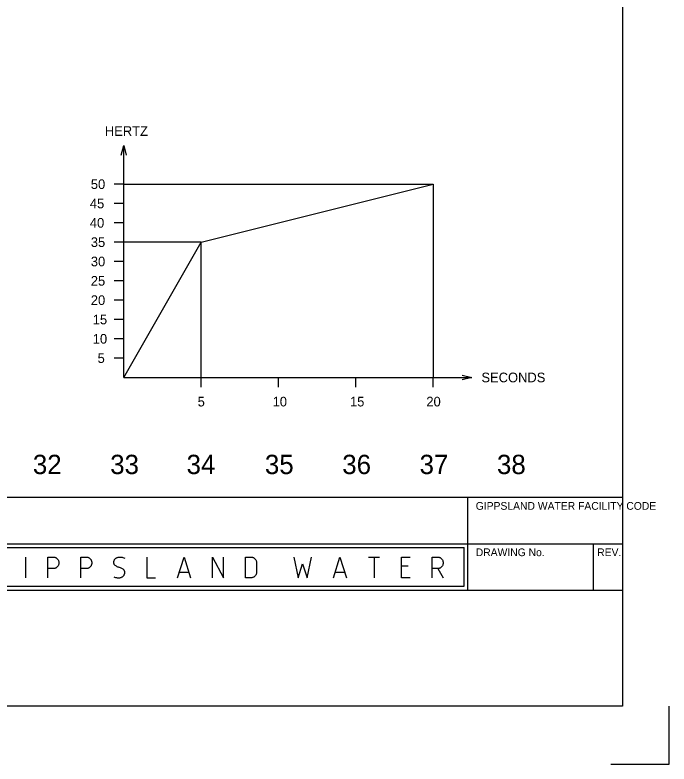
# Model space of a CAD drawing. Extents: x 0 to 841, y 0 to 594.
# Drawn here: x 671.9 to 841, y 0 to 193.8 of the extents above; entities that cross this region are included whole.
import ezdxf

# ---------------------------------------------------------------- set-up
doc = ezdxf.new("R2010")
doc.units = 0
doc.layers.add('A1BORDER', color=7, linetype='Continuous')
doc.layers.add('Level 1', color=7, linetype='Continuous')

msp = doc.modelspace()

# ---------------------------------------------------------------- linework, layer by layer
at = {"layer": 'A1BORDER'}
for p, q in [((829, 581), (829, 15)), ((592.5, 69), (829, 69)), ((789, 45), (789, 69)), ((28, 57), (829, 57)), ((821.5, 45), (821.5, 57)), ((637, 56), (788, 56)), ((788, 46), (788, 56)), ((663, 46), (788, 46)), ((664, 45), (829, 45)), ((829, 15), (28, 15)), ((829, 15), (829, 15)), ((841, 0), (841, 15)), ((826, 0), (841, 0))]:
    msp.add_line(p, q, dxfattribs=at)
for points in [[(674.74, 48.16), (674.74, 53.54)], [(680.42, 48.16), (680.42, 53.54), (681.84, 53.54), (681.96, 53.54), (682.08, 53.52), (682.2, 53.49), (682.32, 53.45), (682.43, 53.4), (682.54, 53.34), (682.65, 53.27), (682.74, 53.19), (682.84, 53.1), (682.92, 53), (682.99, 52.9), (683.06, 52.79), (683.12, 52.67), (683.17, 52.56), (683.21, 52.43), (683.23, 52.31), (683.25, 52.18), (683.26, 52.05), (683.25, 51.91), (683.23, 51.78), (683.21, 51.66), (683.17, 51.53), (683.12, 51.42), (683.06, 51.3), (682.99, 51.19), (682.92, 51.09), (682.84, 50.99), (682.74, 50.9), (682.65, 50.82), (682.54, 50.75), (682.43, 50.69), (682.32, 50.64), (682.2, 50.6), (682.08, 50.57), (681.96, 50.55), (681.84, 50.55), (680.42, 50.55)], [(688.93, 48.16), (688.93, 53.54), (690.35, 53.54), (690.47, 53.54), (690.59, 53.52), (690.71, 53.49), (690.83, 53.45), (690.94, 53.4), (691.05, 53.34), (691.16, 53.27), (691.26, 53.19), (691.35, 53.1), (691.43, 53), (691.51, 52.9), (691.57, 52.79), (691.63, 52.67), (691.68, 52.56), (691.72, 52.43), (691.75, 52.31), (691.76, 52.18), (691.77, 52.05), (691.76, 51.91), (691.75, 51.78), (691.72, 51.66), (691.68, 51.53), (691.63, 51.42), (691.57, 51.3), (691.51, 51.19), (691.43, 51.09), (691.35, 50.99), (691.26, 50.9), (691.16, 50.82), (691.05, 50.75), (690.94, 50.69), (690.83, 50.64), (690.71, 50.6), (690.59, 50.57), (690.47, 50.55), (690.35, 50.55), (688.93, 50.55)], [(697.45, 48.46), (697.67, 48.36), (697.9, 48.27), (698.12, 48.21), (698.36, 48.17), (698.6, 48.16), (698.84, 48.16), (698.87, 48.16), (699.03, 48.18), (699.18, 48.21), (699.33, 48.26), (699.48, 48.32), (699.62, 48.4), (699.72, 48.46), (699.81, 48.53), (699.9, 48.61), (699.98, 48.69), (700.05, 48.78), (700.11, 48.88), (700.17, 48.99), (700.22, 49.09), (700.25, 49.21), (700.28, 49.32), (700.29, 49.36), (700.3, 49.44), (700.3, 49.52), (700.3, 49.61), (700.29, 49.69), (700.27, 49.77), (700.25, 49.86), (700.22, 49.93), (700.18, 50.01), (700.14, 50.09), (700.09, 50.15), (700.04, 50.21), (700.01, 50.25), (699.85, 50.39), (699.69, 50.51), (699.52, 50.61), (699.34, 50.7), (699.15, 50.78), (698.95, 50.83), (698.87, 50.85), (698.68, 50.9), (698.49, 50.96), (698.3, 51.04), (698.12, 51.14), (697.96, 51.26), (697.8, 51.39), (697.73, 51.45), (697.67, 51.51), (697.62, 51.57), (697.58, 51.64), (697.53, 51.71), (697.5, 51.79), (697.47, 51.87), (697.46, 51.95), (697.44, 52.04), (697.43, 52.12), (697.43, 52.21), (697.44, 52.29), (697.45, 52.35), (697.47, 52.46), (697.51, 52.58), (697.55, 52.69), (697.61, 52.79), (697.67, 52.89), (697.74, 52.99), (697.82, 53.07), (697.9, 53.15), (697.99, 53.23), (698.02, 53.24), (698.15, 53.33), (698.3, 53.4), (698.44, 53.45), (698.6, 53.5), (698.75, 53.52), (698.87, 53.54), (699.11, 53.55), (699.35, 53.53), (699.58, 53.49), (699.82, 53.43), (700.04, 53.35), (700.27, 53.25)], [(705.96, 53.54), (705.96, 48.16), (708.23, 48.16)], [(713.91, 48.16), (715.61, 53.54), (717.32, 48.16)], [(722.99, 48.16), (722.99, 53.54), (725.83, 48.16), (725.83, 53.54)], [(731.52, 48.16), (731.52, 53.54), (732.94, 53.54), (733.06, 53.54), (733.18, 53.52), (733.3, 53.49), (733.42, 53.45), (733.53, 53.4), (733.64, 53.34), (733.75, 53.27), (733.84, 53.19), (733.94, 53.1), (734.02, 53), (734.09, 52.9), (734.16, 52.79), (734.22, 52.67), (734.27, 52.56), (734.31, 52.43), (734.33, 52.31), (734.35, 52.18), (734.36, 52.05), (734.36, 49.66), (734.35, 49.52), (734.33, 49.39), (734.31, 49.27), (734.27, 49.14), (734.22, 49.02), (734.16, 48.91), (734.09, 48.8), (734.02, 48.7), (733.94, 48.6), (733.84, 48.51), (733.75, 48.43), (733.64, 48.36), (733.53, 48.3), (733.42, 48.25), (733.3, 48.21), (733.18, 48.18), (733.06, 48.16), (732.94, 48.16), (731.52, 48.16)], [(744.01, 53.54), (745.14, 48.16), (746.28, 51.75), (747.41, 48.16), (748.55, 53.54)], [(754.22, 48.16), (755.92, 53.54), (757.63, 48.16)], [(763.31, 53.54), (766.15, 53.54)], [(764.73, 53.54), (764.73, 48.16)], [(774.09, 48.16), (771.82, 48.16), (771.82, 53.54), (774.09, 53.54)], [(779.78, 48.16), (779.78, 53.54), (781.2, 53.54), (781.32, 53.54), (781.44, 53.52), (781.56, 53.49), (781.68, 53.45), (781.79, 53.4), (781.9, 53.34), (782.01, 53.27), (782.1, 53.19), (782.2, 53.1), (782.28, 53), (782.35, 52.9), (782.42, 52.79), (782.48, 52.67), (782.53, 52.56), (782.56, 52.43), (782.59, 52.31), (782.61, 52.18), (782.61, 52.05), (782.61, 51.91), (782.59, 51.78), (782.56, 51.66), (782.53, 51.53), (782.48, 51.42), (782.42, 51.3), (782.35, 51.19), (782.28, 51.09), (782.2, 50.99), (782.1, 50.9), (782.01, 50.82), (781.9, 50.75), (781.79, 50.69), (781.68, 50.64), (781.56, 50.6), (781.44, 50.57), (781.32, 50.55), (781.2, 50.55), (779.78, 50.55)], [(773.53, 51.15), (771.82, 51.15)], [(781.2, 50.55), (782.61, 48.16)], [(714.48, 49.66), (716.75, 49.66)], [(754.79, 49.66), (757.06, 49.66)]]:
    msp.add_lwpolyline(points, dxfattribs=at)
at = {"layer": 'Level 1'}
for p, q in [((700, 100), (700, 160)), ((700, 150), (697.5, 150)), ((700, 150), (780, 150)), ((720, 135), (780, 150)), ((780, 150), (780, 100)), ((700, 145), (697.5, 145)), ((700, 140), (697.5, 140)), ((700, 135), (697.5, 135)), ((700, 100), (720, 135)), ((720, 135), (700, 135)), ((720, 100), (720, 135)), ((700, 130), (697.5, 130)), ((700, 125), (697.5, 125)), ((700, 120), (697.5, 120)), ((700, 115), (697.5, 115)), ((700, 110), (697.5, 110)), ((700, 105), (697.5, 105)), ((700, 100), (790, 100)), ((720, 97.5), (720, 100)), ((740, 97.5), (740, 100)), ((760, 97.5), (760, 100)), ((780, 97.5), (780, 100))]:
    msp.add_line(p, q, dxfattribs=at)
for points in [[(699.38, 157.5), (700, 160), (700.62, 157.5)], [(787.5, 100.62), (790, 100), (787.5, 99.38)]]:
    msp.add_lwpolyline(points, dxfattribs=at)

# ---------------------------------------------------------------- texts
at = {"layer": 'A1BORDER'}
for s, p in [('GIPPSLAND WATER FACILITY CODE', (791.03, 65.77)), ('DRAWING No.', (791.03, 53.77)), ('REV.', (822.43, 53.77))]:
    msp.add_text(s, height=2, dxfattribs=at).set_placement(p)
at = {"layer": 'Level 1'}
for s, height, p in [('HERTZ', 2.5, (695.14, 162.5)), ('50', 2.5, (691.51, 148.75)), ('45', 2.5, (691.26, 143.75)), ('40', 2.5, (691.26, 138.75)), ('35', 2.5, (691.51, 133.75)), ('30', 2.5, (691.51, 128.75)), ('25', 2.5, (691.51, 123.75)), ('20', 2.5, (691.51, 118.75)), ('15', 2.5, (692.01, 113.75)), ('10', 2.5, (692.01, 108.75)), ('5', 2.5, (693.26, 103.75)), ('SECONDS', 2.5, (792.5, 98.75)), ('5', 2.5, (719.13, 92.5)), ('10', 2.5, (738.51, 92.5)), ('15', 2.5, (758.51, 92.5)), ('20', 2.5, (778.26, 92.5)), ('32', 5, (676.52, 75)), ('33', 5, (696.52, 75)), ('34', 5, (716.27, 75)), ('35', 5, (736.52, 75)), ('36', 5, (756.52, 75)), ('37', 5, (776.52, 75)), ('38', 5, (796.52, 75))]:
    msp.add_text(s, height=height, dxfattribs=at).set_placement(p)

doc.saveas('drawing.dxf')
